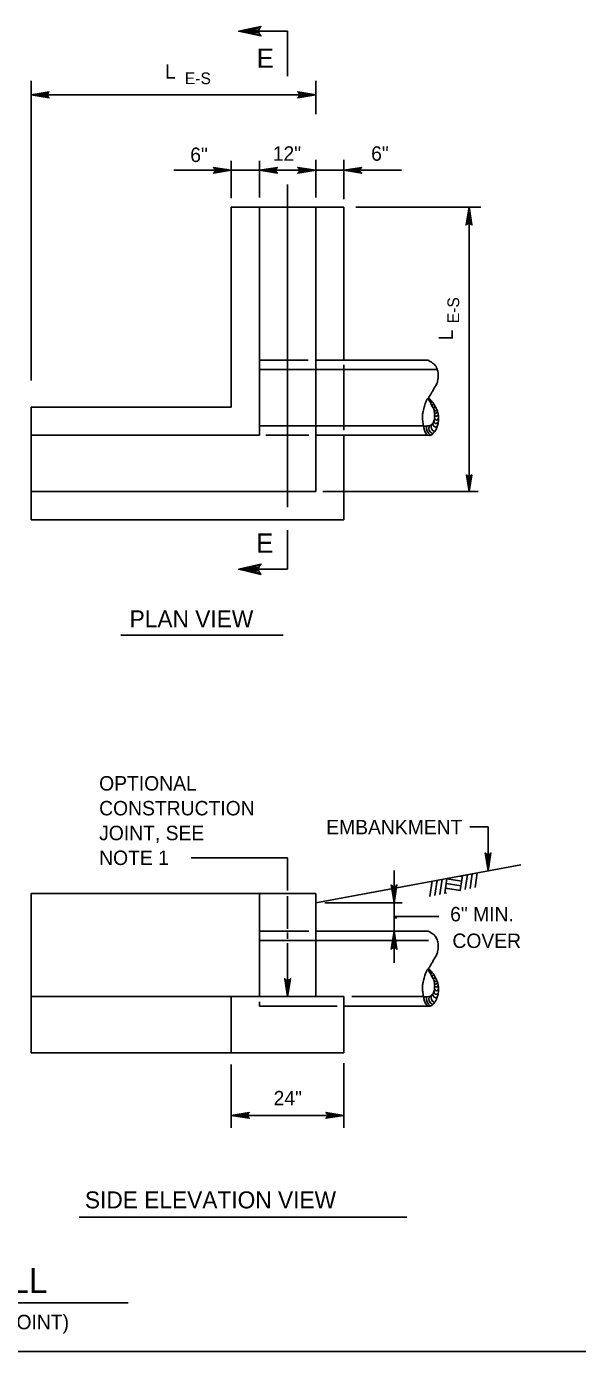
# Model space of a CAD drawing. Extents: x 638877 to 639960, y 297341 to 299123.
# Drawn here: x 639079.3 to 639193.8, y 297950.3 to 298225.8 of the extents above; entities that cross this region are included whole.
import ezdxf

# ---------------------------------------------------------------- set-up
doc = ezdxf.new("R2010")
doc.units = 0
for name, color, linetype in [('1', 7, 'Continuous'), ('2', 7, 'Continuous'), ('3', 7, 'Continuous')]:
    doc.layers.add(name, color=color, linetype=linetype)

msp = doc.modelspace()

# ---------------------------------------------------------------- linework, layer by layer
at = {"layer": '1'}
for p, q in [((639133.53, 298215.47), (639133.53, 298224.79)), ((639133.53, 298192.94), (639133.53, 298125.8)), ((639133.53, 298112.92), (639133.53, 298121.04)), ((639133.53, 298046.12), (639133.53, 298052.93)), ((639171.92, 298049.63), (639171.45, 298046.52)), ((639172.95, 298049.82), (639172.48, 298046.72)), ((639163.58, 298048.08), (639163.1, 298044.9)), ((639164.61, 298048.27), (639164.13, 298045.1)), ((639165.63, 298048.46), (639165.15, 298045.3)), ((639166.65, 298048.65), (639166.18, 298045.5)), ((639169.59, 298047.11), (639166.49, 298047.58)), ((639169.73, 298048.08), (639166.63, 298048.55)), ((639169.88, 298049.05), (639169.3, 298049.14)), ((639169.88, 298049.25), (639169.41, 298046.13)), ((639170.9, 298049.44), (639170.43, 298046.32)), ((639133.53, 298038.19), (639133.53, 298044.96)), ((639166.58, 298045.57), (639166.19, 298045.63)), ((639169.44, 298046.14), (639166.34, 298046.6)), ((639133.53, 298036.07), (639133.53, 298037.39)), ((639133.53, 298024.06), (639133.53, 298035.19)), ((638917.19, 297950.28), (639703.19, 297950.28))]:
    msp.add_line(p, q, dxfattribs=at)
at = {"layer": '2'}
for p, q in [((639133.53, 298224.79), (639123.38, 298224.79)), ((639080.23, 298152.18), (639080.23, 298214.45)), ((639139.38, 298207.57), (639139.38, 298214.45)), ((639080.23, 298211.56), (639139.38, 298211.56)), ((639109.85, 298195.88), (639127.68, 298195.88)), ((639121.83, 298190.04), (639121.83, 298197.87)), ((639127.68, 298190.18), (639127.68, 298197.87)), ((639127.68, 298195.88), (639139.38, 298195.88)), ((639139.38, 298190.18), (639139.38, 298198.02)), ((639139.38, 298195.88), (639157.21, 298195.88)), ((639145.23, 298189.89), (639145.23, 298198.02)), ((639121.83, 298146.62), (639121.83, 298188.22)), ((639121.83, 298188.22), (639145.23, 298188.22)), ((639127.68, 298140.77), (639127.68, 298188.22)), ((639139.38, 298129.07), (639139.38, 298188.22)), ((639145.23, 298156.37), (639145.23, 298188.22)), ((639147.71, 298188.22), (639173.69, 298188.22)), ((639171.23, 298129.07), (639171.23, 298188.22)), ((639127.68, 298156.37), (639137.77, 298156.37)), ((639127.68, 298154.42), (639164.52, 298154.42)), ((639139.38, 298156.37), (639162.78, 298156.37)), ((639145.23, 298141.85), (639145.23, 298155.41)), ((639080.23, 298146.62), (639121.83, 298146.62)), ((639080.23, 298123.22), (639080.23, 298146.62)), ((639080.23, 298140.77), (639127.68, 298140.77)), ((639127.68, 298142.72), (639161.76, 298142.72)), ((639128.99, 298140.77), (639137.93, 298140.77)), ((639139.38, 298140.77), (639162.78, 298140.77)), ((639145.23, 298123.22), (639145.23, 298140.77)), ((639080.23, 298129.07), (639139.38, 298129.07)), ((639140.82, 298129.07), (639173.12, 298129.07)), ((639080.23, 298123.22), (639145.23, 298123.22)), ((639133.53, 298112.92), (639123.38, 298112.92)), ((639171.4, 298059.34), (639175.2, 298059.34)), ((639175.2, 298050.22), (639175.2, 298059.34)), ((639133.53, 298052.93), (639113.45, 298052.93)), ((639139.38, 298043.56), (639182, 298051.49)), ((639155.66, 298043.56), (639155.66, 298050.32)), ((639080.23, 298012.36), (639080.23, 298045.51)), ((639080.23, 298045.51), (639139.38, 298045.51)), ((639127.68, 298024.06), (639127.68, 298045.51)), ((639139.38, 298024.06), (639139.38, 298045.51)), ((639141.27, 298043.56), (639157.33, 298043.56)), ((639155.66, 298037.84), (639155.66, 298043.56)), ((639155.66, 298040.7), (639164.94, 298040.7)), ((639127.68, 298037.71), (639137.92, 298037.71)), ((639127.68, 298035.76), (639162.78, 298035.76)), ((639139.38, 298037.71), (639162.78, 298037.71)), ((639155.66, 298031.08), (639155.66, 298037.84)), ((639080.23, 298024.06), (639145.23, 298024.06)), ((639121.83, 298012.36), (639121.83, 298024.06)), ((639127.68, 298022.11), (639127.68, 298022.97)), ((639127.68, 298022.11), (639143.84, 298022.11)), ((639145.23, 298012.36), (639145.23, 298024.06)), ((639145.23, 298022.11), (639162.78, 298022.11)), ((639146.89, 298024.06), (639161.76, 298024.06)), ((639080.23, 298012.36), (639145.23, 298012.36)), ((639121.83, 297996.76), (639121.83, 298009.97)), ((639145.23, 297996.76), (639145.23, 298010.25)), ((639121.83, 297999.37), (639145.23, 297999.37))]:
    msp.add_line(p, q, dxfattribs=at)
for points in [[(639127.75, 298225.52), (639127.58, 298225.09), (639123.38, 298224.79), (639127.75, 298225.52), (639127.97, 298225.77), (639123.38, 298224.79), (639127.58, 298224.51), (639127.73, 298224.09), (639123.38, 298224.79), (639127.97, 298223.82), (639127.73, 298224.09)], [(639083.77, 298211.11), (639083.64, 298211.37), (639080.23, 298211.56), (639083.77, 298211.11), (639083.95, 298210.96), (639080.23, 298211.56), (639083.63, 298211.73), (639083.76, 298211.98), (639080.23, 298211.56), (639083.95, 298212.15), (639083.76, 298211.98)], [(639135.84, 298212), (639135.97, 298211.74), (639139.38, 298211.56), (639135.84, 298212), (639135.65, 298212.16), (639139.38, 298211.56), (639135.97, 298211.39), (639135.85, 298211.14), (639139.38, 298211.56), (639135.65, 298210.96), (639135.85, 298211.14)], [(639118.29, 298196.33), (639118.42, 298196.07), (639121.83, 298195.88), (639118.29, 298196.33), (639118.1, 298196.48), (639121.83, 298195.88), (639118.42, 298195.71), (639118.3, 298195.46), (639121.83, 298195.88), (639118.1, 298195.29), (639118.3, 298195.46)], [(639131.22, 298195.44), (639131.09, 298195.7), (639127.68, 298195.88), (639131.22, 298195.44), (639131.4, 298195.28), (639127.68, 298195.88), (639131.08, 298196.05), (639131.21, 298196.3), (639127.68, 298195.88), (639131.4, 298196.48), (639131.21, 298196.3)], [(639135.84, 298196.33), (639135.97, 298196.07), (639139.38, 298195.88), (639135.84, 298196.33), (639135.65, 298196.48), (639139.38, 298195.88), (639135.97, 298195.71), (639135.85, 298195.46), (639139.38, 298195.88), (639135.65, 298195.29), (639135.85, 298195.46)], [(639148.77, 298195.44), (639148.64, 298195.7), (639145.23, 298195.88), (639148.77, 298195.44), (639148.95, 298195.28), (639145.23, 298195.88), (639148.63, 298196.05), (639148.76, 298196.3), (639145.23, 298195.88), (639148.95, 298196.48), (639148.76, 298196.3)], [(639170.78, 298184.68), (639171.04, 298184.82), (639171.23, 298188.22), (639170.78, 298184.68), (639170.63, 298184.5), (639171.23, 298188.22), (639171.4, 298184.82), (639171.65, 298184.69), (639171.23, 298188.22), (639171.82, 298184.5), (639171.65, 298184.69)], [(639171.64, 298132.38), (639171.4, 298132.26), (639171.23, 298129.07), (639171.64, 298132.38), (639171.79, 298132.55), (639171.23, 298129.07), (639171.07, 298132.25), (639170.83, 298132.37), (639171.23, 298129.07), (639170.68, 298132.55), (639170.83, 298132.37)], [(639127.75, 298113.72), (639127.58, 298113.26), (639123.38, 298112.92), (639127.75, 298113.72), (639127.97, 298113.99), (639123.38, 298112.92), (639127.58, 298112.61), (639127.73, 298112.16), (639123.38, 298112.92), (639127.97, 298111.85), (639127.73, 298112.16)], [(639175.64, 298053.76), (639175.39, 298053.63), (639175.2, 298050.22), (639175.64, 298053.76), (639175.8, 298053.94), (639175.2, 298050.22), (639175.03, 298053.63), (639174.78, 298053.75), (639175.2, 298050.22), (639174.61, 298053.94), (639174.78, 298053.75)], [(639156.1, 298047.1), (639155.85, 298046.96), (639155.66, 298043.56), (639156.1, 298047.1), (639156.26, 298047.28), (639155.66, 298043.56), (639155.49, 298046.96), (639155.24, 298047.09), (639155.66, 298043.56), (639155.07, 298047.28), (639155.24, 298047.09)], [(639156.1, 298034.11), (639155.85, 298034.24), (639155.66, 298037.65), (639156.1, 298034.11), (639156.26, 298033.92), (639155.66, 298037.65), (639155.49, 298034.24), (639155.24, 298034.12), (639155.66, 298037.65), (639155.07, 298033.92), (639155.24, 298034.12)], [(639133.97, 298027.6), (639133.71, 298027.46), (639133.53, 298024.06), (639133.97, 298027.6), (639134.13, 298027.78), (639133.53, 298024.06), (639133.36, 298027.46), (639133.11, 298027.59), (639133.53, 298024.06), (639132.93, 298027.78), (639133.11, 298027.59)], [(639125.37, 297998.93), (639125.24, 297999.19), (639121.83, 297999.37), (639125.37, 297998.93), (639125.55, 297998.77), (639121.83, 297999.37), (639125.23, 297999.54), (639125.36, 297999.79), (639121.83, 297999.37), (639125.55, 297999.97), (639125.36, 297999.79)], [(639141.69, 297999.82), (639141.82, 297999.56), (639145.23, 297999.37), (639141.69, 297999.82), (639141.5, 297999.97), (639145.23, 297999.37), (639141.82, 297999.2), (639141.7, 297998.95), (639145.23, 297999.37), (639141.5, 297998.78), (639141.7, 297998.95)]]:
    msp.add_lwpolyline(points, dxfattribs=at)
for centre, radius, start, end in [((639163.15, 298147.97), 0.127, 176.947, 93.053), ((639163.25, 298147.84), 0.298, 285.6074, 325.806), ((639163.64, 298147.22), 0.173, 195.7562, 33.8551), ((639163.96, 298146.69), 0.174, 203.3341, 43.8053), ((639164.22, 298146.11), 0.253, 188.5456, 52.8367), ((639164.4, 298143.16), 0.667, 173.2089, 278.5784), ((639164.36, 298143.65), 0.415, 171.0795, 335.4873), ((639164.3, 298145.61), 0.291, 223.7085, 2.3299), ((639164.48, 298144.31), 0.359, 199.7004, 348.5016), ((639164.43, 298145.03), 0.315, 212.411, 346.6825), ((639164.06, 298142.26), 1.67, 168.491, 237.5129), ((639164.05, 298142.24), 1.18, 158.8965, 245.9336), ((639164.54, 298142.62), 1.18, 164.8508, 242.5231), ((639163.15, 298029.3), 0.127, 176.947, 93.053), ((639163.25, 298029.17), 0.298, 285.6074, 325.806), ((639163.64, 298028.55), 0.173, 195.7562, 33.8551), ((639163.96, 298028.02), 0.174, 203.3341, 43.8053), ((639164.22, 298027.44), 0.253, 188.5456, 52.8367), ((639164.36, 298024.98), 0.415, 171.0795, 335.4873), ((639164.3, 298026.94), 0.291, 223.7085, 2.3299), ((639164.48, 298025.64), 0.359, 199.7004, 348.5016), ((639164.43, 298026.36), 0.315, 212.411, 346.6825), ((639164.06, 298023.59), 1.67, 168.491, 237.5129), ((639164.05, 298023.57), 1.18, 158.8965, 245.9336), ((639164.54, 298023.95), 1.18, 164.8508, 242.5231), ((639164.4, 298024.49), 0.667, 173.2089, 278.5784)]:
    msp.add_arc(centre, radius, start, end, dxfattribs=at)
for points in [[(639162.78, 298156.37), (639163.28, 298156.03), (639163.8, 298155.7), (639164.38, 298155.05), (639164.74, 298154.1), (639164.76, 298152.31), (639164.47, 298151.34), (639164.02, 298150.62), (639163.61, 298149.86), (639163.31, 298149.34), (639163.04, 298148.88), (639162.78, 298148.57), (639162.38, 298147.98), (639162.14, 298147.36), (639161.83, 298146.34), (639161.69, 298145.72), (639161.57, 298144.98), (639161.57, 298144.43), (639161.64, 298143.5), (639161.83, 298142.52), (639161.99, 298141.81), (639162.35, 298141.07), (639162.78, 298140.77), (639163.33, 298140.81), (639163.85, 298141.26), (639164.28, 298141.79), (639164.57, 298142.4), (639164.81, 298143.22), (639164.88, 298144.19), (639164.85, 298145), (639164.59, 298146), (639164.21, 298146.74), (639163.85, 298147.41), (639163.4, 298147.93), (639162.78, 298148.57)], [(639161.76, 298142.72), (639162.23, 298142.69), (639162.85, 298142.74), (639163.19, 298142.79), (639163.45, 298143.03), (639163.64, 298143.22), (639163.83, 298143.52), (639163.97, 298143.95), (639164.07, 298144.41), (639164.09, 298144.91), (639164.09, 298145.33), (639164, 298145.79), (639163.9, 298146.22), (639163.73, 298146.53), (639163.42, 298147.07), (639163.33, 298147.34), (639163.23, 298147.57), (639162.97, 298147.98), (639162.85, 298148.26), (639162.78, 298148.57)], [(639162.78, 298037.71), (639163.28, 298037.36), (639163.8, 298037.03), (639164.38, 298036.38), (639164.74, 298035.43), (639164.76, 298033.64), (639164.47, 298032.67), (639164.02, 298031.95), (639163.61, 298031.19), (639163.31, 298030.67), (639163.04, 298030.21), (639162.78, 298029.91), (639162.38, 298029.31), (639162.14, 298028.69), (639161.83, 298027.67), (639161.69, 298027.05), (639161.57, 298026.31), (639161.57, 298025.76), (639161.64, 298024.83), (639161.83, 298023.85), (639161.99, 298023.14), (639162.35, 298022.4), (639162.78, 298022.11), (639163.33, 298022.14), (639163.85, 298022.59), (639164.28, 298023.12), (639164.57, 298023.74), (639164.81, 298024.55), (639164.88, 298025.52), (639164.85, 298026.33), (639164.59, 298027.33), (639164.21, 298028.07), (639163.85, 298028.74), (639163.4, 298029.26), (639162.78, 298029.91)], [(639161.76, 298024.06), (639162.23, 298024.02), (639162.85, 298024.07), (639163.19, 298024.12), (639163.45, 298024.36), (639163.64, 298024.55), (639163.83, 298024.86), (639163.97, 298025.28), (639164.07, 298025.74), (639164.09, 298026.24), (639164.09, 298026.67), (639164, 298027.12), (639163.9, 298027.55), (639163.73, 298027.86), (639163.42, 298028.4), (639163.33, 298028.67), (639163.23, 298028.9), (639162.97, 298029.31), (639162.85, 298029.6), (639162.78, 298029.91)]]:
    msp.add_spline(points, degree=3, dxfattribs=at)
at = {"layer": '3'}
for p, q in [((639098.84, 298099.25), (639132.62, 298099.25)), ((639090.23, 297978.21), (639158.32, 297978.21)), ((639013.06, 297960.43), (639100.36, 297960.43))]:
    msp.add_line(p, q, dxfattribs=at)

# ---------------------------------------------------------------- texts
at = {"layer": '1'}
msp.add_text('E-S', height=2.43, dxfattribs=at).set_placement((639112.17, 298213.78))
msp.add_text('E-S', height=2.43, rotation=90, dxfattribs=at).set_placement((639169.18, 298164.07))
at = {"layer": '2'}
msp.add_text('L', height=3, rotation=90, dxfattribs=at).set_placement((639167.91, 298160.53))
msp.add_text('.', height=3.9, dxfattribs=at).set_placement((639155.27, 298040.28))
at = {"layer": '3'}
for s, height, p in [('E', 3.99, (639127.11, 298217.19)), ('L', 3, (639108.05, 298214.9)), ('E', 3.99, (639126.99, 298116.37)), ('PLAN VIEW', 3.53, (639100.69, 298100.84)), ('OPTIONAL', 3, (639094.36, 298066.91)), ('CONSTRUCTION', 2.9999, (639094.36, 298061.75)), ('EMBANKMENT', 3, (639141.55, 298057.81)), ('JOINT, SEE', 3, (639094.36, 298056.59)), ('NOTE 1', 3, (639094.36, 298051.43)), ('6" MIN.', 3, (639167.31, 298039.72)), ('COVER', 3, (639167.78, 298034.18)), ('24"', 3, (639130.62, 298001.46)), ('SIDE ELEVATION VIEW', 3.5299, (639091.4, 297980.04)), ('TYPE E-S ENDWALL', 5.1858, (639016.54, 297962.46)), ('(WITH OPTIONAL CONSTRUCTION JOINT)', 2.9999, (639007.65, 297954.91))]:
    msp.add_text(s, height=height, dxfattribs=at).set_placement(p)
for s, p in [('6"', (639113.29, 298197.59)), ('12"', (639130.44, 298197.85)), ('6"', (639150.89, 298197.85))]:
    msp.add_text(s, height=3, rotation=360, dxfattribs=at).set_placement(p)

doc.saveas('drawing.dxf')
